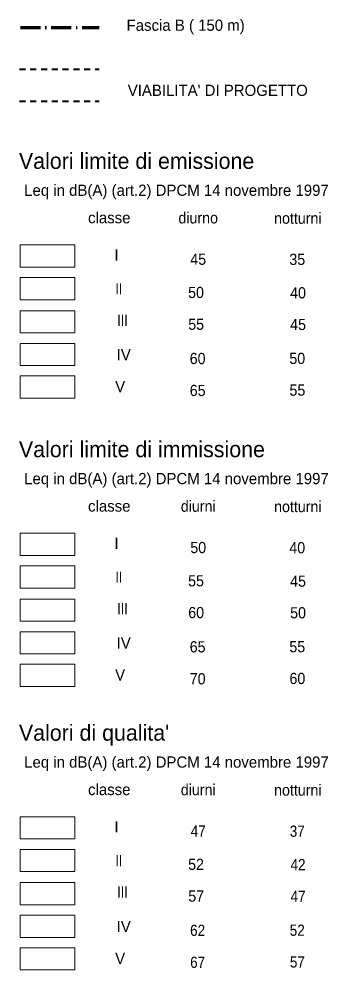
# Model space of a CAD drawing. Extents: x 645880 to 658994, y 884400 to 894744.
# Drawn here: x 650157 to 650930, y 889959 to 892336 of the extents above; entities that cross this region are included whole.
import ezdxf
from ezdxf.enums import TextEntityAlignment as Align

# ---------------------------------------------------------------- set-up
doc = ezdxf.new("R2010")
doc.units = 0
doc.header["$LTSCALE"] = 10
doc.linetypes.add('DOT_DASHED', pattern=[7.7, 5, -1.2, 0.3, -1.2])
doc.linetypes.add('SHORT_DASHED', pattern=[2.7, 1.5, -1.2])
doc.layers.add('62', color=7, linetype='Continuous', lineweight=35)

msp = doc.modelspace()

# ---------------------------------------------------------------- linework, layer by layer
at = {"layer": '62', "linetype": 'DOT_DASHED', "lineweight": 70}
msp.add_line((650160.69, 892315.03), (650357.53, 892315.03), dxfattribs=at)
at = {"layer": '62', "linetype": 'SHORT_DASHED', "lineweight": 40}
for p, q in [((650158.17, 892210.49), (650357.53, 892210.49)), ((650158.17, 892130.49), (650357.53, 892130.49))]:
    msp.add_line(p, q, dxfattribs=at)
at = {"layer": '62', "lineweight": 13}
for points in [[(650159.51, 891771.29), (650296.59, 891771.29), (650296.59, 891715.85), (650159.51, 891715.85)], [(650159.51, 891689.89), (650296.59, 891689.89), (650296.59, 891634.45), (650159.51, 891634.45)], [(650159.51, 891606.73), (650296.59, 891606.73), (650296.59, 891551.29), (650159.51, 891551.29)], [(650159.51, 891525.29), (650296.59, 891525.29), (650296.59, 891469.85), (650159.51, 891469.85)], [(650159.51, 891443.85), (650296.59, 891443.85), (650296.59, 891388.41), (650159.51, 891388.41)], [(650159.51, 891050.77), (650296.59, 891050.77), (650296.59, 890995.33), (650159.51, 890995.33)], [(650159.51, 890969.37), (650296.59, 890969.37), (650296.59, 890913.93), (650159.51, 890913.93)], [(650159.51, 890886.21), (650296.59, 890886.21), (650296.59, 890830.77), (650159.51, 890830.77)], [(650159.51, 890804.77), (650296.59, 890804.77), (650296.59, 890749.33), (650159.51, 890749.33)], [(650159.51, 890723.33), (650296.59, 890723.33), (650296.59, 890667.89), (650159.51, 890667.89)], [(650159.51, 890342.35), (650296.59, 890342.35), (650296.59, 890286.91), (650159.51, 890286.91)], [(650159.51, 890260.95), (650296.59, 890260.95), (650296.59, 890205.51), (650159.51, 890205.51)], [(650159.51, 890177.79), (650296.59, 890177.79), (650296.59, 890122.35), (650159.51, 890122.35)], [(650159.51, 890096.35), (650296.59, 890096.35), (650296.59, 890040.91), (650159.51, 890040.91)], [(650159.51, 890014.91), (650296.59, 890014.91), (650296.59, 889959.47), (650159.51, 889959.47)]]:
    msp.add_lwpolyline(points, close=True, dxfattribs=at)

# ---------------------------------------------------------------- texts
at = {"layer": '62'}
for s, height, p in [('Fascia B ( 150 m)', 28, (650426.01, 892306.38)), ("VIABILITA' DI PROGETTO", 28, (650428.95, 892143.68)), ('Valori limite di emissione', 40, (650156.77, 891961.36)), ('Leq in dB(A) (art.2) DPCM 14 novembre 1997', 28, (650169.93, 891894)), ('Valori limite di immissione', 40, (650156.77, 891240.84)), ('Leq in dB(A) (art.2) DPCM 14 novembre 1997', 28, (650169.93, 891173.48)), ("Valori di qualita'", 40, (650156.77, 890532.4)), ('Leq in dB(A) (art.2) DPCM 14 novembre 1997', 28, (650169.93, 890465.04))]:
    msp.add_text(s, height=height, dxfattribs=at).set_placement(p)
for s, p in [('classe', (650382.75, 891825.36)), ('I', (650400.79, 891732.3)), ('IV', (650418.96, 891483.18)), ('V', (650409.97, 891403.3)), ('classe', (650382.75, 891104.84)), ('I', (650400.79, 891011.78)), ('IV', (650418.96, 890762.66)), ('V', (650409.97, 890682.78)), ('classe', (650382.75, 890396.4)), ('I', (650400.79, 890303.34)), ('IV', (650418.96, 890054.22)), ('V', (650409.97, 889974.34))]:
    msp.add_text(s, height=28, dxfattribs=at).set_placement(p, align=Align.CENTER)
for s, width, p in [('diurno', 0.95, (650605.2, 891824.96)), ('notturni', 0.95, (650854.31, 891824.08)), ('45', 0.95, (650605.2, 891721.64)), ('35', 0.95, (650852.88, 891721.28)), ('II', 0.8, (650406.67, 891647.66)), (' 50', 0.95, (650594.77, 891638.56)), ('40', 0.95, (650854.84, 891637.68)), ('III', 0.85, (650415.88, 891569.06)), (' 55', 0.95, (650595.13, 891559.12)), ('45', 0.95, (650854.92, 891558.6)), ('60', 0.95, (650603.68, 891473.52)), ('50', 0.95, (650852.84, 891473.8)), ('65', 0.95, (650603.8, 891393.72)), ('55', 0.95, (650853.2, 891394.56)), ('diurni', 0.95, (650605.18, 891104.44)), ('notturni', 0.95, (650854.31, 891103.56)), ('50', 0.95, (650605.2, 891001.12)), ('40', 0.95, (650852.88, 891000.76)), ('II', 0.8, (650406.67, 890927.14)), (' 55', 0.95, (650594.77, 890918.04)), ('45', 0.95, (650854.84, 890917.16)), ('III', 0.85, (650415.88, 890848.54)), (' 60', 0.95, (650595.13, 890838.6)), ('50', 0.95, (650854.92, 890838.08)), ('65', 0.95, (650603.68, 890753)), ('55', 0.95, (650852.84, 890753.28)), ('70', 0.95, (650603.8, 890673.2)), ('60', 0.95, (650853.2, 890674.04)), ('diurni', 0.95, (650605.18, 890396)), ('notturni', 0.95, (650854.31, 890395.12)), ('47', 0.9, (650605.19, 890292.68)), ('37', 0.9, (650852.87, 890292.32)), ('II', 0.8, (650406.67, 890218.7)), (' 52', 0.95, (650594.78, 890209.6)), ('42', 0.9, (650854.83, 890208.72)), ('III', 0.85, (650415.88, 890140.1)), (' 57', 0.95, (650595.14, 890130.16)), ('47', 0.9, (650854.91, 890129.64)), ('62', 0.9, (650603.67, 890044.56)), ('52', 0.9, (650852.83, 890044.84)), ('67', 0.9, (650603.79, 889964.76)), ('57', 0.9, (650853.19, 889965.6))]:
    msp.add_text(s, height=28, dxfattribs=dict(at, width=width)).set_placement(p, align=Align.CENTER)

doc.saveas('drawing.dxf')
